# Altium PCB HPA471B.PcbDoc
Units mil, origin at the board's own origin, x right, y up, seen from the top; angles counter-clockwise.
Board outline 1305 x 1105 mil, 2 copper layers (Top Layer, Bottom Layer); 47 components, 32 nets, 115 pads, 21 vias.
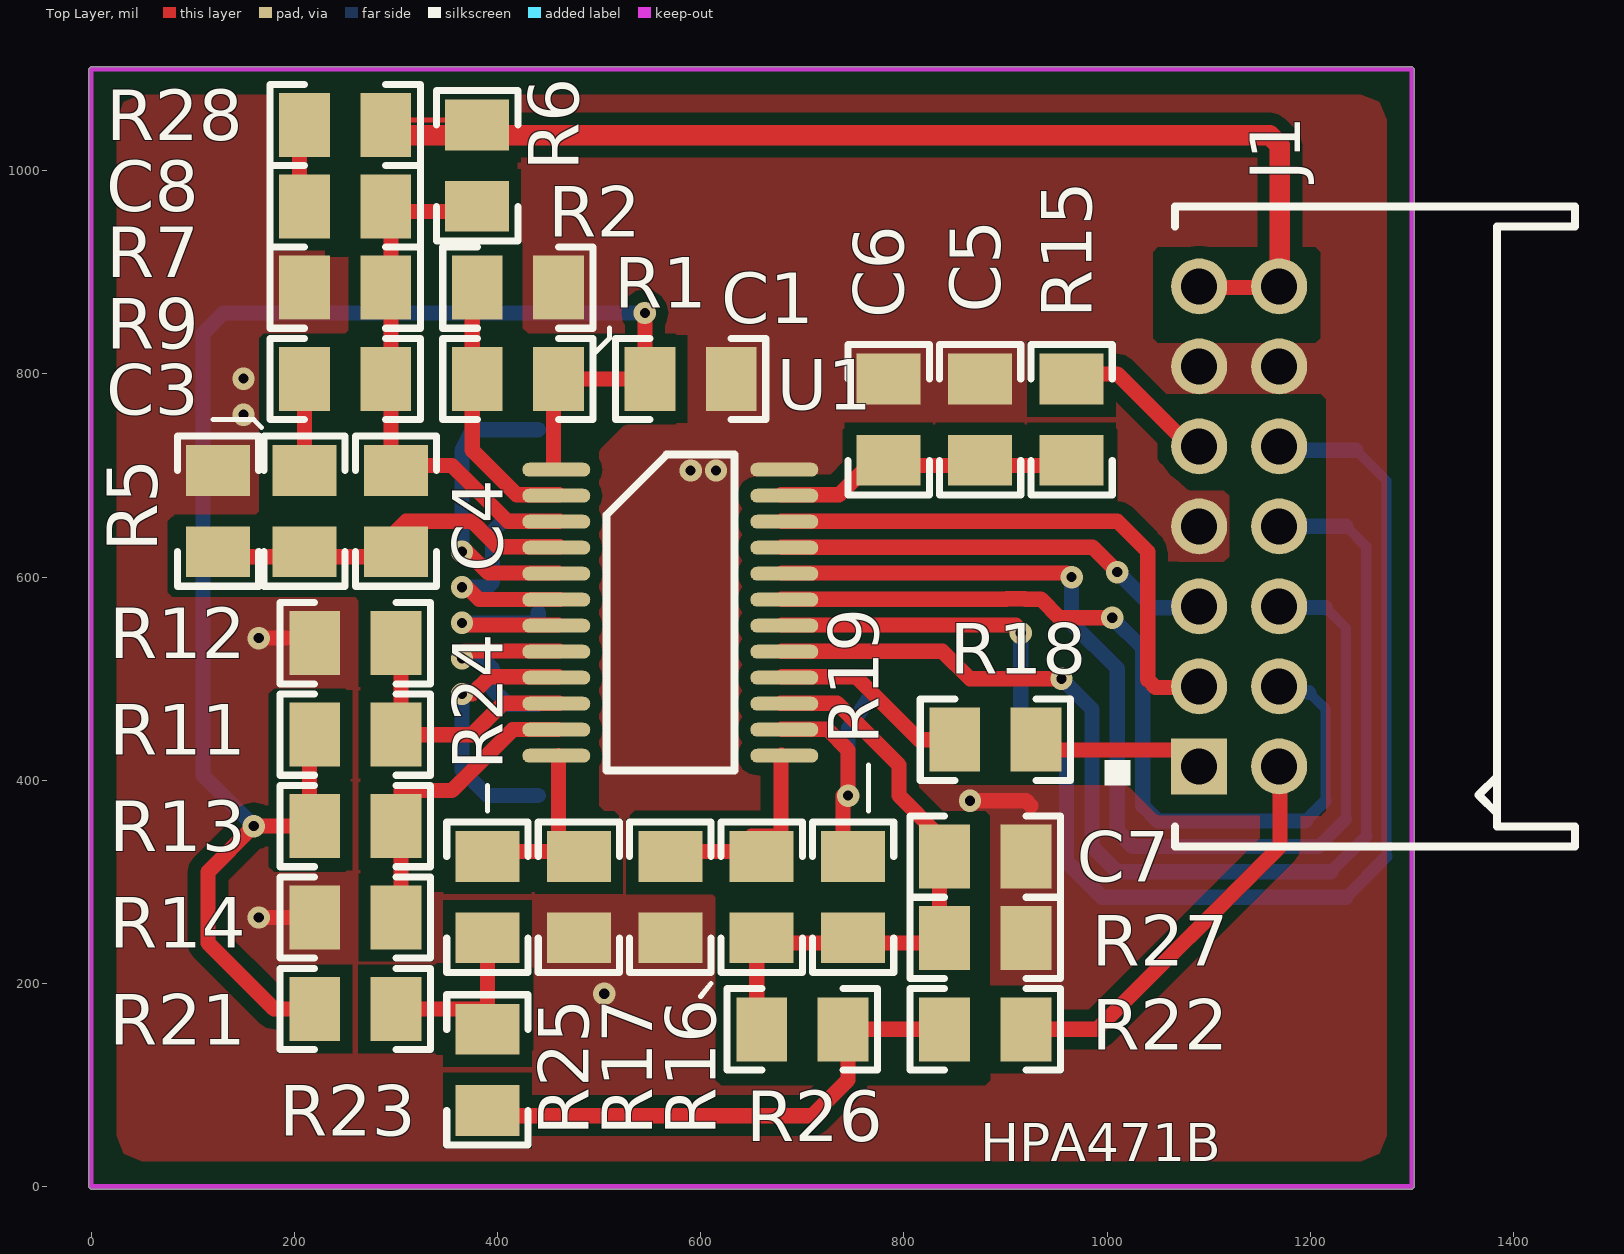
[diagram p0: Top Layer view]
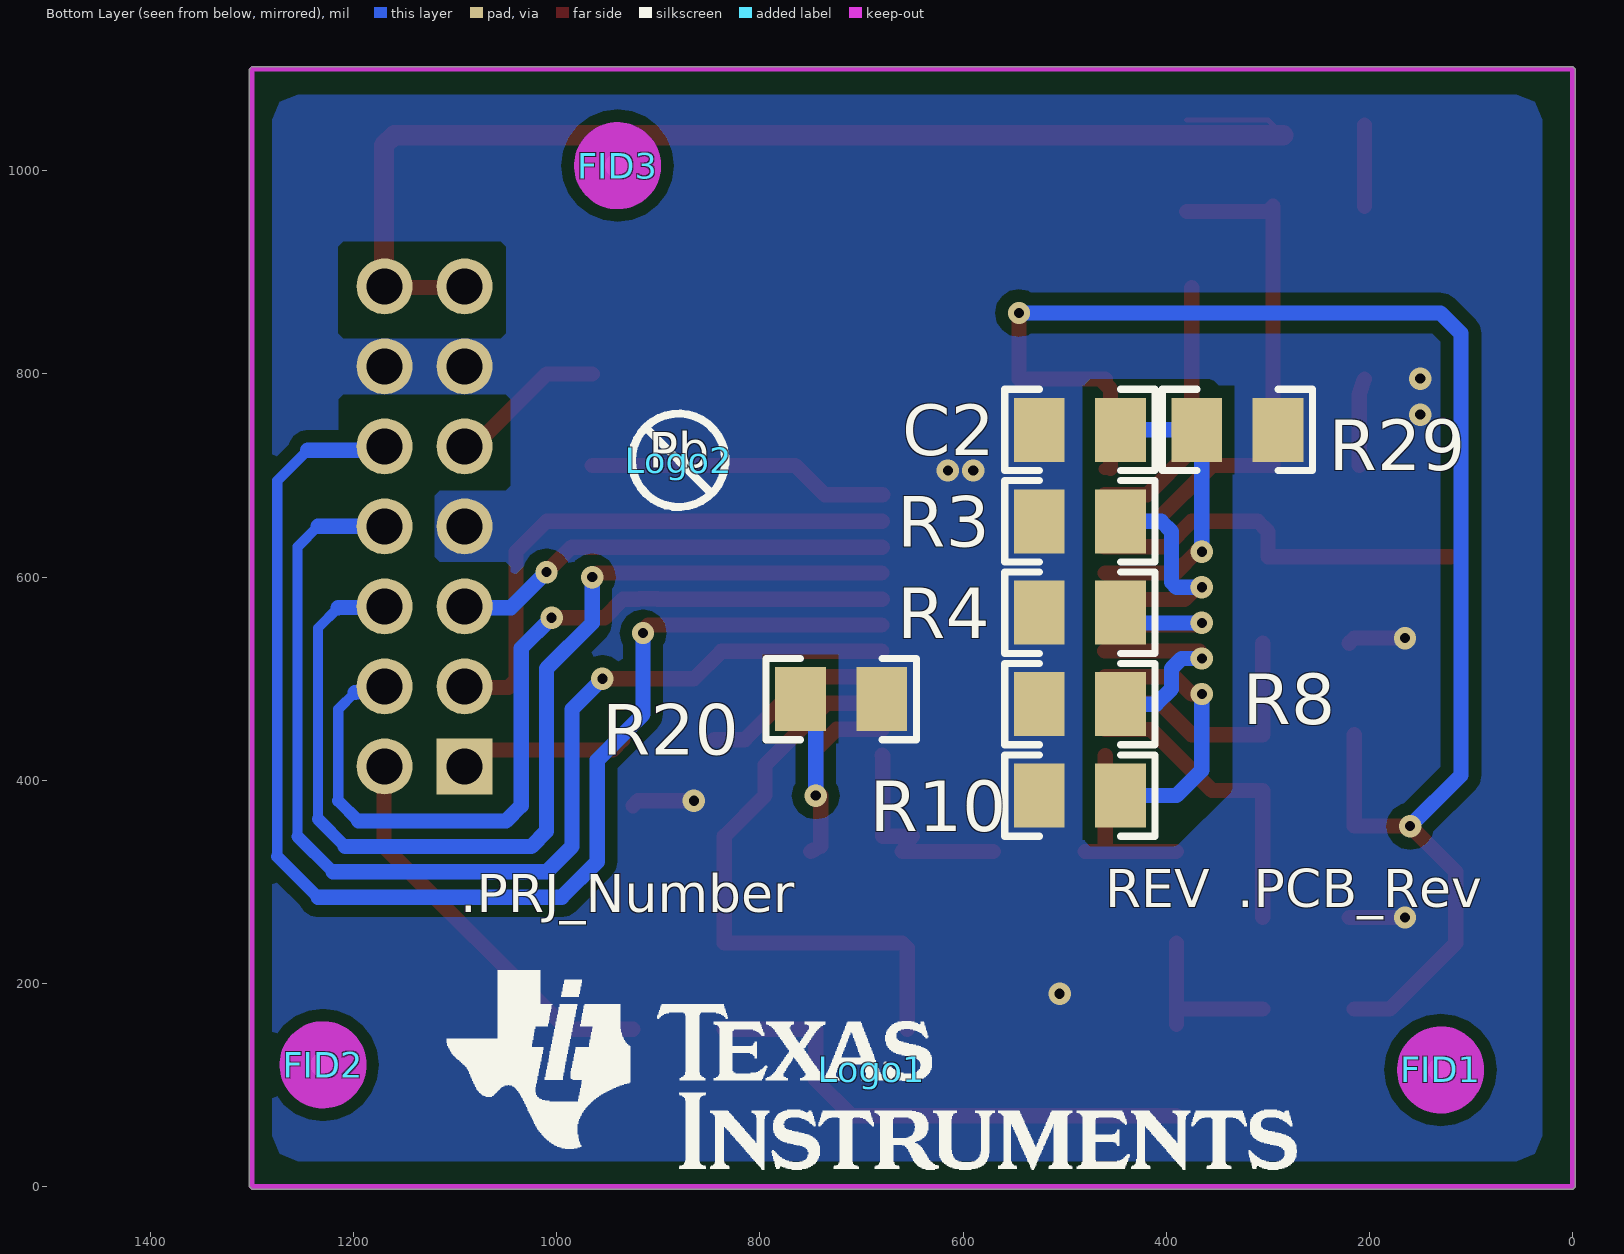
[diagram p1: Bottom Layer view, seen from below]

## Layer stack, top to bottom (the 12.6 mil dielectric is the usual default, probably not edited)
Top Layer: signal copper 2.8
Dielectric: core 12.6, FR-4, Dk 4.8
Bottom Layer: signal copper 2.8

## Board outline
-2.5,0 0,-2.5 1300,-2.5 1302.5,0 1302.5,1100 1300,1102.5 0,1102.5 -2.5,1100

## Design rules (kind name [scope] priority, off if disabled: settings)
AcuteAngle [All] p1: minimum=4.50000000000000E+0001 checktracksonly=TRUE
AssemblyTestPointUsage [All] p1: valid=2
Clearance Clearance_Poly [InPolygon] p1: gap=12
Clearance Clearance_BoardEdge_Poly [OnCopper and InPoly vs IsKeepOut] p2: gap=19.68
Clearance Clearance_BoardEdge [OnCopper and Not InComponentClass('Logo') and not InComponentClass('FiducialMark') and not InRegion(1000,500,4000,800) and Not IsKeepout vs IsKeepout] p3 off: gap=19.68
Clearance Clearance_ALL [All] p4: gap=8
ComponentClearance ComponentClearance_Logo [InComponentClass(Logo)] p1: gap=3.94 collisioncheckmode=3 verticalgap=27.56 showdistances=FALSE
ComponentClearance ComponentClearance_ScrewToNut [(HasFootprint('NY PMS 440 0025 PH')) vs (HasFootprint('Keystone_1902C'))] p2: gap=0 collisioncheckmode=3 verticalgap=0 showdistances=FALSE
ComponentClearance ComponentClearance_MountingHoles [InComponentClass('Mounting Holes')] p3: gap=19.68 collisioncheckmode=3 verticalgap=27.56 showdistances=FALSE
ComponentClearance ComponentClearance_SmallPassives [HasFootprint('0201*') or HasFootprint('0402*') or HasFootprint('0508') or HasFootprint('0603*') or HasFootprint('0612') or HasFootprint('0805*') or HasFootprint('0815*') or HasFootprint('0830*') or HasFootprint('1206*') or HasFootprint('1210*') or HasFootprint('1808*') or HasFootprint('1812*') or HasFootprint('1825*') or HasFootprint('2010*') or HasFootprint('2220*') or HasFootprint('2225*') or HasFootprint('2512*') or HasFootprint('2728*') or HasFootprint('3518*') vs HasFootprint('0201*') or HasFootprint('0402*') or HasFootprint('0508') or HasFootprint('0603*') or HasFootprint('0612') or HasFootprint('0805*') or HasFootprint('0815*') or HasFootprint('0830*') or HasFootprint('1206*') or HasFootprint('1210*') or HasFootprint('1808*') or HasFootprint('1812*') or HasFootprint('1825*') or HasFootprint('2010*') or HasFootprint('2220*') or HasFootprint('2225*') or HasFootprint('2512*') or HasFootprint('2728*') or HasFootprint('3518*')] p4: gap=7.87 collisioncheckmode=3 verticalgap=10 showdistances=FALSE
ComponentClearance ComponentClearance_THtoSMT [IsThruComponent vs IsSMTComponent] p5 off: gap=7.87 collisioncheckmode=3 verticalgap=27.56 showdistances=FALSE
ComponentClearance ComponentClearance_THtoTH [IsThruComponent vs IsThruComponent] p6 off: gap=7.87 collisioncheckmode=3 verticalgap=27.56 showdistances=FALSE
ComponentClearance [All] p7: gap=0 collisioncheckmode=3 verticalgap=0 showdistances=FALSE
DiffPairsRouting [All] p1: maxlimit=100 minlimit=10 mostfreqgap=10 maxuncoupledlength=1000
FabricationTestPointUsage TestPointUsage [All] p1: valid=2 allowmultiple=FALSE
FabricationTestpoint Testpoint [All] p1: side=3 testpointundercomponent=TRUE minsize=40 maxsize=100 preferedsize=60 minholesize=0 maxholesize=40 preferedholesize=32 testpointgrid=1 allowsidetop=TRUE allowsidebottom=TRUE usegrid=TRUE gridtolerance=0.01
FanoutControl Fanout_LCC [IsLCC] p1: bgadir=Out bgaviamode=Centered fanoutstyle=Auto fanoutdirection=Alternating viagrid=1 // Fanout_LCC (Default Rule)
FanoutControl Fanout_BGA [IsBGA] p2: bgadir=Out bgaviamode=Centered fanoutstyle=Auto fanoutdirection=Alternating viagrid=1 // Fanout_BGA (Default Rule)
FanoutControl Fanout_Default [All] p4: bgadir=Out bgaviamode=Centered fanoutstyle=Auto fanoutdirection=Alternating viagrid=1 // Fanout_Default (Default Rule)
FanoutControl Fanout_Small [(CompPinCount < 5)] p5: bgadir=Out bgaviamode=Centered fanoutstyle=Auto fanoutdirection=OutThenIn viagrid=1 // Fanout_Small (Default Rule)
Height "Height Bottom" [(OnLayer('Bottom Layer'))] p1: minheight=0 maxheight=1000 prefheight=500
Height Height_top [(OnLayer('Top Layer'))] p2: minheight=0 maxheight=1750 prefheight=1750
HoleSize [All] p1: absolutevalues=TRUE maxlimit=275.59 minlimit=8 maxpercent=80.000 minpercent=20.000
MinimumAnnularRing [All] p1: minimumring=6
MinimumSolderMaskSliver MinimumSolderMaskSliver_Logo [InComponentClass('Logo') vs InComponentClass('Logo')] p1: minsoldermaskwidth=0.7
MinimumSolderMaskSliver [All] p2: minsoldermaskwidth=4
PlaneConnect [All] p1: planeconnectstyle=Relief reliefexpansion=10 reliefentries=4 reliefconductorwidth=10 reliefairgap=10
PolygonConnect PolygonConnect_23 [All vs IsNamedPolygon('Top Layer, Top-PWRGND 4')] p1: connectstyle=Direct reliefconductorwidth=10 reliefentries=4 polygonreliefangle="90 Angle" airgapwidth=10
PolygonConnect PolygonConnect_22 [All vs IsNamedPolygon('Top Layer, Top-PWRGND 4')] p2: connectstyle=Direct reliefconductorwidth=10 reliefentries=4 polygonreliefangle="90 Angle" airgapwidth=10
PolygonConnect PolygonConnect_21 [All vs IsNamedPolygon('Top Layer, Top-PWRGND 2')] p3: connectstyle=Direct reliefconductorwidth=10 reliefentries=4 polygonreliefangle="90 Angle" airgapwidth=10
PolygonConnect PolygonConnect_20 [All vs IsNamedPolygon('Top Layer, Top-PWRGND 3')] p4: connectstyle=Direct reliefconductorwidth=10 reliefentries=4 polygonreliefangle="90 Angle" airgapwidth=10
PolygonConnect PolygonConnect_19 [All vs IsNamedPolygon('Top Layer, Top-PWRGND 4')] p5: connectstyle=Direct reliefconductorwidth=10 reliefentries=4 polygonreliefangle="90 Angle" airgapwidth=10
PolygonConnect PolygonConnect_18 [All vs IsNamedPolygon('Top Layer, Top-GND')] p6: connectstyle=Direct reliefconductorwidth=10 reliefentries=4 polygonreliefangle="90 Angle" airgapwidth=10
PolygonConnect PolygonConnect_17 [All vs IsNamedPolygon('Top Layer, Top-GND 1')] p7: connectstyle=Direct reliefconductorwidth=10 reliefentries=4 polygonreliefangle="90 Angle" airgapwidth=10
PolygonConnect PolygonConnect_16 [All vs IsNamedPolygon('Top Layer, Top-GND 2')] p8: connectstyle=Direct reliefconductorwidth=10 reliefentries=4 polygonreliefangle="90 Angle" airgapwidth=10
PolygonConnect PolygonConnect_15 [All vs IsNamedPolygon('Top Layer, Top-NET00002')] p9: connectstyle=Direct reliefconductorwidth=10 reliefentries=4 polygonreliefangle="90 Angle" airgapwidth=10
PolygonConnect PolygonConnect_14 [All vs IsNamedPolygon('Top Layer, Top-NET00003')] p10: connectstyle=Direct reliefconductorwidth=10 reliefentries=4 polygonreliefangle="90 Angle" airgapwidth=10
PolygonConnect PolygonConnect_13 [All vs IsNamedPolygon('Top Layer, Top-NET00003')] p11: connectstyle=Direct reliefconductorwidth=10 reliefentries=4 polygonreliefangle="90 Angle" airgapwidth=10
PolygonConnect PolygonConnect_12 [All vs IsNamedPolygon('Top Layer, Top-NET00007')] p12: connectstyle=Direct reliefconductorwidth=10 reliefentries=4 polygonreliefangle="90 Angle" airgapwidth=10
PolygonConnect PolygonConnect_11 [All vs IsNamedPolygon('Top Layer, Top-NET00016')] p13: connectstyle=Direct reliefconductorwidth=10 reliefentries=4 polygonreliefangle="90 Angle" airgapwidth=10
PolygonConnect PolygonConnect_10 [All vs IsNamedPolygon('Top Layer, Top-NET00025')] p14: connectstyle=Direct reliefconductorwidth=10 reliefentries=4 polygonreliefangle="90 Angle" airgapwidth=10
PolygonConnect PolygonConnect_9 [All vs IsNamedPolygon('Top Layer, Top-NET00025 1')] p15: connectstyle=Direct reliefconductorwidth=10 reliefentries=4 polygonreliefangle="90 Angle" airgapwidth=10
PolygonConnect PolygonConnect_8 [All vs IsNamedPolygon('Top Layer, Top-No Net')] p16: connectstyle=Direct reliefconductorwidth=10 reliefentries=4 polygonreliefangle="90 Angle" airgapwidth=10
PolygonConnect PolygonConnect_7 [All vs IsNamedPolygon('Top Layer, Top-PWRGND')] p17: connectstyle=Direct reliefconductorwidth=10 reliefentries=4 polygonreliefangle="90 Angle" airgapwidth=10
PolygonConnect PolygonConnect_6 [All vs IsNamedPolygon('Top Layer, Top-PWRGND 1')] p18: connectstyle=Direct reliefconductorwidth=10 reliefentries=4 polygonreliefangle="90 Angle" airgapwidth=10
PolygonConnect PolygonConnect_5 [All vs IsNamedPolygon('Top Layer, Top-PWRGND 2')] p19: connectstyle=Direct reliefconductorwidth=10 reliefentries=4 polygonreliefangle="90 Angle" airgapwidth=10
PolygonConnect PolygonConnect_4 [All vs IsNamedPolygon('Top Layer, Top-PWRGND 3')] p20: connectstyle=Direct reliefconductorwidth=10 reliefentries=4 polygonreliefangle="90 Angle" airgapwidth=10
PolygonConnect PolygonConnect_3 [All vs IsNamedPolygon('Top Layer, Top-PWRGND 4')] p21: connectstyle=Direct reliefconductorwidth=10 reliefentries=4 polygonreliefangle="90 Angle" airgapwidth=10
PolygonConnect PolygonConnect_2 [All vs IsNamedPolygon('Top Layer, Top-PWRGND 3') Or  IsNamedPolygon('Top Layer, Top-PWRGND 4')] p22: connectstyle=Direct reliefconductorwidth=10 reliefentries=4 polygonreliefangle="90 Angle" airgapwidth=10
PolygonConnect PolygonConnect_1 [All vs IsNamedPolygon('Top Layer, Top-PWRGND 2') Or  IsNamedPolygon('Bottom Layer, Bottom-GND') Or  IsNamedPolygon('Bottom Layer, Bottom-NET00038') Or  IsNamedPolygon('Bottom Layer, Bottom-NET00006') Or  IsNamedPolygon('Bottom Layer, Bottom-NET00003') Or  IsNamedPolygon('Bottom Layer, Bottom-NET00004 2') Or  IsNamedPolygon('Bottom Layer, Bottom-NET00020') Or  IsNamedPolygon('Bottom Layer, Bottom-GND 2') Or  IsNamedPolygon('Bottom Layer, Bottom-NET00004') Or  IsNamedPolygon('Bottom Layer, Bottom-PWRGND') Or  IsNamedPolygon('Bottom Layer, Bottom-NET00002 1') Or  IsNamedPolygon('Bottom Layer, Bottom-NET00013') Or  IsNamedPolygon('Bottom Layer, Bottom-NET00012') Or  IsNamedPolygon('Bottom Layer, Bottom-NET00004 3') Or  IsNamedPolygon('Bottom Layer, Bottom-NET00004 1') Or  IsNamedPolygon('Bottom Layer, Bottom-NET00016') Or  IsNamedPolygon('Bottom Layer, Bottom-GND 1') Or  IsNamedPolygon('Bottom Layer, Bottom-NET00025') Or  IsNamedPolygon('Bottom Layer, Bottom-NET00002') Or  IsNamedPolygon('Top Layer, Top-No Net') Or  IsNamedPolygon('Top Layer, Top-NET00016') Or  IsNamedPolygon('Top Layer, Top-NET00025 1') Or  IsNamedPolygon('Top Layer, Top-GND 2') Or  IsNamedPolygon('Top Layer, Top-PWRGND 3') Or  IsNamedPolygon('Top Layer, Top-PWRGND 4') Or  IsNamedPolygon('Top Layer, Top-NET00002') Or  IsNamedPolygon('Top Layer, Top-NET00007') Or  IsNamedPolygon('Top Layer, Top-GND 1') Or  IsNamedPolygon('Top Layer, Top-PWRGND 1') Or  IsNamedPolygon('Top Layer, Top-GND') Or  IsNamedPolygon('Top Layer, Top-NET00025') Or  IsNamedPolygon('Top Layer, Top-NET00003') Or  IsNamedPolygon('Top Layer, Top-PWRGND')] p23: connectstyle=Direct reliefconductorwidth=10 reliefentries=4 polygonreliefangle="90 Angle" airgapwidth=10
PolygonConnect [All] p24: connectstyle=Relief reliefconductorwidth=10 reliefentries=4 polygonreliefangle="90 Angle" airgapwidth=10
RoutingVias [All] p1: holewidth=16 width=34 viastyle="Through Hole" minholewidth=6 minwidth=10 maxholewidth=40 maxwidth=65
SMDToCorner [All] p1 off: distance=30000
SilkToSilkClearance [All] p1 off: silktosilkclearance=4.5
SilkscreenOverComponentPads [All] p1 off: minsilkscreentomaskgap=5
SolderMaskExpansion [All] p1: expansion=3
Width [All] p1: maxlimit=100 minlimit=10 preferedwidth=31.5 checkconnectedcopper=TRUE
13 further rules are at their usual default settings.

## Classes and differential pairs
component class HPA471B_Hardware: !PCB FID1 FID2 FID3 Logo1 Logo2 ZZ1 ZZ2 ZZ3
component class HPA471B_Sht01: C1 C2 C3 C4 C5 C6 C7 C8 J1 R1 R2 R3 R4 R5 R6 R7 R8 R9 R10 R11 R12 R13 R14 R15 R16 R17 R18 R19 R20 R21 R22 R23 R24 R25 R26 R27 R28 R29 U1

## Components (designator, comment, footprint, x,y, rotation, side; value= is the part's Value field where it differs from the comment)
C1 "08055C105KAT2A" 0805_HV 590,795 r180 top
C2 "C0805C154K5RACTU" 0805_HV 485,745 r180 bottom
C3 "08055C562KAT2A" 0805_HV 210,665 r90 top
C4 "08055C561KAT2A" 0805_HV 300,665 r90 top
C5 "08055C105KAT2A" 0805_HV 875,755 r270 top
C6 "08053C104KAT2A" 0805_HV 785,755 r270 top
C7 "08055C331KAT2A" 0805_HV 880,325 r180 top
C8 "08055C331KAT2A" 0805_HV 250,965 r180 top
FID1 "Fiducial" Fiducial6.4-20 130,115 r180 bottom
FID2 "Fiducial" Fiducial6.4-20 1230,120 r180 bottom
FID3 "Fiducial" Fiducial6.4-20 940,1005 r180 bottom
J1 "DF11-14DP-2DS(52)" Hirose_DF11-14DP-2DS_52 1130,650 r90 top
Logo1 "Texas Instruments" TI_Stacked_Overlay_Small 690,115 r180 bottom
Logo2 "Pb-Free Symbol" Pb-Free_Overlay_Small 880,715 r180 bottom
R1 "CRCW08052K37FKEA" 0805_HV 420,795 r0 top
R2 "CRCW08052K37FKEA" 0805_HV 420,885 r180 top
R3 "CRCW080512K1FKEA" 0805_HV 485,655 r180 bottom
R4 "CRCW080512K1FKEA" 0805_HV 485,565 r180 bottom
R5 "CRCW08051K00FKEA" 0805_HV 125,665 r90 top
R6 "CRCW08059K09FKEA" 0805_HV 380,1005 r90 top
R7 "CRCW08052K37FKEA" 0805_HV 250,885 r0 top
R8 "CRCW080556K2FKEA" 0805_HV 485,475 r180 bottom
R9 "CRCW080527K4FKEA" 0805_HV 250,795 r0 top
R10 "CRCW080513K3FKEA" 0805_HV 485,385 r180 bottom
R11 "CRCW080561K9FKEA" 0805_HV 260,445 r0 top
R12 "CRCW08051K00FKEA" 0805_HV 260,535 r0 top
R13 "CRCW08051K00FKEA" 0805_HV 260,355 r180 top
R14 "CRCW0805127KFKEA" 0805_HV 260,265 r0 top
R15 "CRCW080522R6FKEA" 0805_HV 965,755 r90 top
R16 "CRCW08051K00FKEA" 0805_HV 660,285 r270 top
R17 "CRCW08050000Z0EA" 0805_HV 570,285 r90 top
R18 "CRCW08051K00FKEA" 0805_HV 890,440 r0 top
R19 "CRCW08051K00FKEA" 0805_HV 750,285 r270 top
R20 "CRCW08050000Z0EA" 0805_HV 720,480 r0 bottom
R21 "CRCW08050000Z0EA" 0805_HV 260,175 r180 top
R22 "CRCW08051K00FKEA" 0805_HV 880,155 r0 top
R23 "CRCW08051K00FKEA" 0805_HV 390,115 r270 top
R24 "CRCW080516K9FKEA" 0805_HV 390,285 r270 top
R25 "CRCW08051K00FKEA" 0805_HV 480,285 r90 top
R26 "CRCW08050000Z0EA" 0805_HV 700,155 r0 top
R27 "CRCW08051K00FKEA" 0805_HV 880,245 r180 top
R28 "CRCW08051K00FKEA" 0805_HV 250,1045 r0 top
R29 "CRCW0805825KFKEA" 0805_HV 330,745 r0 bottom
U1 "UCC28950PW" PW0024A_N 570,565 r0 top
ZZ1 "These assemblies are ESD sensitive, ESD precautions shall be observed." AssemblyNote -120,6695 r0 top
ZZ2 "These assemblies must be clean and free from flux and all contaminants. Use of no clean flux is not acceptable." AssemblyNote -120,6590 r0 top
ZZ3 "These assemblies must comply with workmanship standards IPC-A-610 Class 2, unless otherwise specified." AssemblyNote -120,6470 r0 top

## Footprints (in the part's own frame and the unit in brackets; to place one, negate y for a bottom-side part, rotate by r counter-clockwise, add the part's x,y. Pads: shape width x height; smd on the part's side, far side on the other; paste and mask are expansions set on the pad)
0805_HV [mil] "0805 with 30mil clearance between pads"
  rect 50x63 smd: 1(-40,0) 2(40,0)
  silkscreen extent -74,-40 74,40, body extent -43,-29 43,29, height 43
AssemblyNote [mil] "Assembly Note"
Fiducial6.4-20 [mil]
  round 25 smd mask+26.87: 1(0,0)
  Top Layer keep-out circle w46.37: c0,0 r19.68
Hirose_DF11-14DP-2DS_52 [mm] "TH, 14-Leads, Body 16x10mm, Pitch 2mm"
  rect 1.4x1.4 hole 0.9: 1(-6,1)
  round 1.4 hole 0.9: 2(-6,-1) 3(-4,1) 4(-4,-1) 5(-2,1) 6(-2,-1) 7(0,1) 8(0,-1) 9(2,1) 10(2,-1) 11(4,1) 12(4,-1) 13(6,1) 14(6,-1)
  silkscreen extent -8,-8.4 8,1.6, body extent -8,-8.4 8,1.6, height 5
Pb-Free_Overlay_Small [mil]
  silkscreen extent -46,-46 46,46
PW0024A_N [mm] "TSOP, 24-Leads, Body 7.8x4.4mm, Pitch 0.65mm, IPC Medium Density"
  oval 1.7x0.35 smd: 1(-2.85,3.575) 2(-2.85,2.925) 3(-2.85,2.275) 4(-2.85,1.625) 5(-2.85,0.975) 6(-2.85,0.325) 7(-2.85,-0.325) 8(-2.85,-0.975) 9(-2.85,-1.625) 10(-2.85,-2.275) 11(-2.85,-2.925) 12(-2.85,-3.575) 13(2.85,-3.575) 14(2.85,-2.925) 15(2.85,-2.275) 16(2.85,-1.625) 17(2.85,-0.975) 18(2.85,-0.325) 19(2.85,0.325) 20(2.85,0.975) 21(2.85,1.625) 22(2.85,2.275) 23(2.85,2.925) 24(2.85,3.575)
  silkscreen extent -1.6,-3.95 1.6,3.95, body extent -3.21,-3.9 3.21,3.9, height 0.98
TI_Stacked_Overlay_Small [mil]
  silkscreen extent -418,-98 418,98

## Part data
C1 C5: "CAP, CERM, 1 µF, 50 V, +/- 10%, X7R, 0805"
C2: "CAP, CERM, 0.15 µF, 50 V, +/- 10%, X7R, 0805"
C3: "CAP, CERM, 5600 pF, 50 V, +/- 10%, X7R, 0805"
C4: "CAP, CERM, 560 pF, 50 V, +/- 10%, X7R, 0805"
C6: "CAP, CERM, 0.1 µF, 25 V, +/- 10%, X7R, 0805"
C7 C8: "CAP, CERM, 330 pF, 50 V, +/- 10%, X7R, 0805"
FID1 FID2 FID3: "Fiducial mark.  There is nothing to buy or mount."
J1: "Header (shrouded), 2 mm, 7x2, R/A, TH"
Logo1: library part TI_Logo, "Texas Instrument Corporate Signature"
Logo2: library part Pb-Free
R1 R2 R7: "RES, 2.37k ohm, 1%, 0.125W, 0805"
R3 R4: "RES, 12.1k ohm, 1%, 0.125W, 0805"
R5 R12 R13 R16 R18 R19 R22 R23 R25 R27 R28: "RES, 1.00k ohm, 1%, 0.125W, 0805"
R6: "RES, 9.09k ohm, 1%, 0.125W, 0805"
R8: "RES, 56.2k ohm, 1%, 0.125W, 0805"
R9: "RES, 27.4k ohm, 1%, 0.125W, 0805"
R10: "RES, 13.3 k, 1%, 0.125 W, 0805"
R11: "RES, 61.9k ohm, 1%, 0.125W, 0805"
R14: "RES, 127k ohm, 1%, 0.125W, 0805"
R15: "RES, 22.6 ohm, 1%, 0.125W, 0805"
R17 R20 R21 R26: "RES, 0 ohm, 5%, 0.125W, 0805"
R24: "RES, 16.9k ohm, 1%, 0.125W, 0805"
R29: "RES, 825k ohm, 1%, 0.125W, 0805"
U1: "Green Phase-Shifted Full-Bridge Controller with Synchronous Rectification with Current Control, 97 % Duty Cycle, -40 to +125 degC, 24-pin TSSOP (PW), Green (RoHS & no Sb/Br)"
ZZ1 ZZ2 ZZ3: library part AssemblyNote

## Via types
v1: diameter 22, hole 10, Top Layer to Bottom Layer, 21 vias

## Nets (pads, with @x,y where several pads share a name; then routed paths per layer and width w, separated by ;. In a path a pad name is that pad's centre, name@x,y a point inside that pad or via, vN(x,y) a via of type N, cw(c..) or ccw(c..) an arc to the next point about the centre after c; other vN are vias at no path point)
ADEL: R19.1 R20.2 U1.14 | length 286.1
  Top Layer w15: U1.14@679.5,450.3 724.7,450.3 745,430 v1(745,385) 740,385 740,335 R19.1@750,330
  Bottom Layer w15: v1(745,385) 745,450 R20.2@765,480
ADELEF: R16.1 R17.2 U1.13 | length 216.9
  Top Layer w15: R17.2@570,330 660,330 650,345 679,345 679,424.2 U1.13@679.5,424.7
COMP: C3.1 C4.1 R5.1 U1.4 | length 381.1
  Top Layer w12: U1.4@460.5,629.6 U1.4@461,630
  Top Layer w15: R5.1@120,620 300,620 300,645 310,655 375,655 400,630 U1.4@461,630
CS: J1.2 R22.2 | length 402.1
  Top Layer w15: R22.2@925,155 990,155 1170,335 1170,415 J1.2@1168.7,412.8
CS0: C7.2 R16.2 R19.2 R26.1 R27.2 U1.15 | length 595.4
  Top Layer w12: U1.15@679,476 U1.15@679.5,475.9
  Top Layer w15: R26.1@655,155 655,235 660,240 665,240 750,240 795,240 835,240 835,245 835,325 835,345 795,385 795,415 734,476 U1.15@679,476
DCM: R24.1 R25.2 U1.12 | length 184.3
  Top Layer w15: R24.1@390,330 R25.2@460,330 ; U1.12@460,424.25 R25.2@460,330 ; R25.2@480,330 R25.2@460,330
DELAB: R3.2 U1.6 | length 234.7
  Top Layer w12: U1.6@460.5,578.4 U1.6@462,578
  Top Layer w15: v1(365,590) 370,590 382,578 U1.6@462,578
  Bottom Layer w15: v1(365,590) 390,590 395,595 395,645 405,655 R3.2@440,655
DELCD: R4.2 U1.7 | length 182.5
  Top Layer w12: U1.7@460,553 U1.7@460.5,552.8
  Top Layer w15: v1(365,555) 365,553 U1.7@460,553
  Bottom Layer w15: v1(365,555) 440,555 R4.2@440,565
DELEF: R8.2 U1.8 | length 206.2
  Top Layer w15: v1(365,520) 367.2,527.2 U1.8@460.5,527.2
  Bottom Layer w15: v1(365,520) 385,520 395,510 395,490 410,475 R8.2@440,475
EA+: R1.1 R2.2 U1.2 | length 263.9
  Top Layer w15: R2.2@375,885 375,725 419,681 460.5,681 U1.2@460.5,680.8
EA-: C4.2 C8.1 R6.1 R7.2 R9.2 U1.3 | length 531.4
  Top Layer w12: U1.3@460.5,655.2 U1.3@461,655
  Top Layer w15: R6.1@380,960 300,960 295,965 295,885 295,795 295,710 300,710 355,710 410,655 U1.3@461,655
GND: C1.1 C2.1 C5.1 C6.1 C7.1 J1.7 J1.11 J1.12 R2.1 R3.1 R4.1 R5.2 R7.1 R8.1 R10.1 R12.1 R14.1 R17.1 R20.1 R25.1 R27.1 R29.1 U1.24 | length 174.1
  Top Layer w15: v1(165,265) R14.1 ; v1(165,540) 215,540 R12.1 ; v1(865,380) 920,380 925,375
  other v1: 505,190 590,705 615,705 150,760 150,795.42
NetC3_2: C3.2 R9.1 | length 85.8
  Top Layer w15: R9.1@205,795 210,780 C3.2@210,710
NetC8_2: C8.2 R28.1 | length 80
  Top Layer w15: C8.2@205,965 R28.1@205,1045
NetR21_1: R21.1 R23.1 R24.2 | length 165
  Top Layer w15: R21.1@305,175 R23.1@390,175 ; R23.1@390,160 R23.1@390,175 ; R24.2@390,240 R23.1@390,175
NetR22_1: R22.1 R23.2 R26.2 | length 509.5
  Top Layer w15: R23.2@390,70 710,70 745,105 745,155 R22.1@835,155
OUTA: J1.3 U1.22 | length 552
  Top Layer w15: U1.22@679.5,655.1 1010,655 1040,625 1040,499 1047.5,491.5 J1.3@1090,491.5
OUTB: J1.5 U1.21 | length 436.1
  Top Layer w12: U1.21@679.5,629.5 U1.21@680,630
  Top Layer w15: U1.21@679.5,629.5 985.5,629.5 v1(1010,605)
  Bottom Layer w15: v1(1010,605) 1045,570 1090,570 J1.5@1090,570.2
OUTC: J1.6 U1.20 | length 1060.5
  Top Layer w12: U1.20@679.5,603.9 U1.20@680,604
  Top Layer w15: U1.20@680,604 960,604 v1(965,600)
  Bottom Layer w10: 1215,570 1235,550 1235,361.98
  Bottom Layer w12: 1208.02,335 1235,361.98
  Bottom Layer w15: v1(965,600) 965,555 1010,510 1010,350 1025,335 1208.02,335 ; J1.6@1168.7,570.2 1215,570
OUTD: J1.4 U1.19 | length 869
  Top Layer w15: U1.19@679.5,578.3 900.66,578.3 901.19,578.84 918.81,578.84 919.34,578.3 934.7,578.3 953,560 v1(1005,560)
  Bottom Layer w10: 1198.5,486.5 1215,470 1215,380
  Bottom Layer w12: 1195,360 1215,380
  Bottom Layer w15: v1(1005,560) 1035,530 1035,375 1050,360 1195,360 ; J1.4@1168.7,491.5 1198.5,486.5
OUTE: J1.10 U1.18 | length 1321.9
  Top Layer w12: U1.18@679.5,552.7 U1.18@680,553
  Top Layer w15: U1.18@680,553 910,553 v1(915,545)
  Bottom Layer w10: 1245,725 1275,695 1275,325
  Bottom Layer w12: 1235,285 1275,325
  Bottom Layer w15: v1(915,545) 915,465 960,420 960,320 995,285 1235,285 ; J1.10@1168.7,727.6 1170,730 1175,725 1245,725
OUTF: J1.8 U1.17 | length 1139.1
  Top Layer w12: U1.17@679.5,527.1 U1.17@680,527
  Top Layer w15: U1.17@680,527 838,527 865,500 v1(955,500)
  Bottom Layer w10: 1235,650 1255,630 1255,344.83
  Bottom Layer w12: 1220.17,310 1255,344.83
  Bottom Layer w15: v1(955,500) 985,470 985,335 1010,310 1220.17,310 ; J1.8@1168.7,648.9 1170,650 1235,650
RSUM: R13.1 R14.2 U1.11 | length 305.5
  Top Layer w12: U1.11@460,450 U1.11@460.5,450.4
  Top Layer w15: R14.2@305,265 305,355 305,390 355,390 415,450 U1.11@460,450
RT: R11.2 R12.2 U1.10 | length 258.8
  Top Layer w12: U1.10@460.5,476 U1.10@461,476
  Top Layer w15: R12.2@305,535 305,445 375,445 406,476 U1.10@460.5,476
SS/EN: C2.2 R29.2 U1.5 | length 291.6
  Top Layer w12: U1.5@460,604 U1.5@460.5,604
  Top Layer w15: v1(365,625) 370,625 391,604 U1.5@460,604
  Bottom Layer w15: v1(365,625) 365,725 375,745 C2.2@440,745
SYNC: J1.1 R18.2 | length 173.4
  Top Layer w15: R18.2@935,440 945,430 1085,430 1090,425 J1.1@1090,412.8
SYNC0: R18.1 U1.16 | length 191.4
  Top Layer w12: U1.16@679.5,501.5 U1.16@680,502
  Top Layer w15: U1.16@680,502 753,502 815,440 R18.1@845,440
TMIN: R10.2 U1.9 | length 263
  Top Layer w12: U1.9@460,502 U1.9@460.5,501.6
  Top Layer w15: v1(365,485) 375,485 392,502 U1.9@460,502
  Bottom Layer w15: v1(365,485) 365,410 390,385 R10.2@440,385
VBIAS: J1.9 R15.2 | length 156.4
  Top Layer w15: R15.2@965,800 1010,800 1080,730 1090,730 J1.9@1090,727.6
VDD: C5.2 C6.2 R15.1 U1.23 | length 298.6
  Top Layer w12: U1.23@679,681 U1.23@679.5,680.7
  Top Layer w15: U1.23@679,681 736,681 765,710 785,710 875,710 R15.1@965,710
VOUT: J1.13 J1.14 R6.2 R28.2 | length 1227.4
  Top Layer w5: R28.2@285,1035 300,1050 R6.2@380,1050
  Top Layer w15: J1.13@1090,885 1168.7,885 J1.14@1170,885 ; J1.14@1175,890 J1.14@1180,895
  Top Layer w20: R28.2@285,1035 1160,1035 1170,1025 1170,885 1175,885 J1.14@1175,890
VREF: C1.2 R1.2 R11.1 R13.2 R21.2 U1.1 | length 1602.4
  Top Layer w12: U1.1@455,707 455.6,706.4 U1.1@460.5,706.4
  Top Layer w15: R21.2@215,175 180,175 115,240 115,310 v1(160,355) 215,355 R11.1@215,445 ; U1.1@455,707 455,785 R1.2@465,795 ; R1.2 R1.2@465,795 ; v1(545,860) 545,795 R1.2@465,795
  Bottom Layer w15: v1(160,355) 110,405 110,840 130,860 v1(545,860)
pads on no net: FID1.1 FID2.1 FID3.1

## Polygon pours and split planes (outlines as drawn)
GND on Top Layer "Top Layer, Top-GND 2" (solid, remove dead copper, pour order 6): 25,50 32.32,32.32 50,25 1250,25 1267.68,32.32 1275,50 1275,1050 1267.68,1067.68 1250,1075 50,1075 32.32,1067.68 25,1050
GND on Top Layer "Top Layer, Top-GND 1" (solid, pour order 4): 1060,830 1055,825 1055,790 1060,785 1200,785 1205,790 1205,825 1200,830
GND on Top Layer "Top Layer, Top-GND" (solid, pour order 2): 1055,690 1050,685 1050,637.07 1051.47,633.54 1073.54,611.46 1077.07,610 1115,610 1120,615 1120,685 1115,690
GND on Bottom Layer "Bottom Layer, Bottom-GND 2" (solid, remove dead copper, pour order 12): 30,50 37.32,32.32 55,25 1255,25 1272.68,32.32 1280,50 1280,1050 1272.68,1067.68 1255,1075 55,1075 37.32,1067.68 30,1050
GND on Bottom Layer "Bottom Layer, Bottom-GND 1" (solid, pour order 10): 1050,830 1045,825 1045,790 1050,785 1215,785 1220,790 1220,825 1215,830
GND on Bottom Layer "Bottom Layer, Bottom-GND" (solid, pour order 8): 1055,690 1050,685 1050,637.07 1051.47,633.54 1073.54,611.46 1077.07,610 1115,610 1120,615 1120,685 1115,690

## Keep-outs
Keep-Out Layer, Board:
  lines w5: 0,0 1300,0 1300,1100 0,1100 0,0

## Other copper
Top Layer:
  pour cut-out: 505,370 500,375 500,415 500,722.93 501.47,726.46 523.54,748.54 527.07,750 575,750 580,755 580,835 575,840 430,840 425,845 425,927.93 423.53,931.46 410.35,944.65 409.59,945.27 396.26,954.16 393.49,955 310,955 305,950 305,935 300,930 260,930 255,925 255,845 250,840 170,840 165,835 165,665 160,660 80,660 75,655 75,585 80,580 260,580 265,575 265,295 270,290 515,290 520,295 520,365 515,370
  pour cut-out: 225,1075 230,915 420,920 420,1075
  pour cut-out: 1048.54,366.46 1052.07,365 1210,365 1215,370 1215,775 1210,780 1055,780 1050,775 1050,717.07 1051.47,713.54 1078.54,686.46 1082.07,685 1115,685 1120,680 1120,620 1115,615 1055,615 1050,610 1050,485 1045,480 850,480 845,475 845,400 850,395 1017.93,395 1021.46,393.54
  pour cut-out: 1005,655 1010,660 1010,745 1005,750 745,750 740,745 740,660 745,655
  pour cut-out: 1050,925 1045,920 1045,835 1050,830 1205,830 1210,835 1210,920 1205,925
  pour cut-out: 615,105 620,100 880,100 885,105 885,365 880,370 535,370 530,365 530,295 535,290 610,290 615,285
  pour cut-out: 175,315 180,310 250,310 255,315 255,485 250,490 180,490 175,485
  pour cut-out: 430,130 435,135 435,215 430,220 340,220 335,215 335,135 340,130
Bottom Layer:
  pour cut-out: 1045,370 1050,365 1210,365 1215,370 1215,775 1210,780 1050,780 1045,775 1045,690 1050,685 1115,685 1120,680 1120,620 1115,615 1050,615 1045,610
  pour cut-out: 1055,930 1050,925 1050,840 1055,835 1210,835 1215,840 1215,925 1210,930
  pour cut-out: 357.07,795 353.54,793.54 336.47,776.46 335,772.93 335,392.07 336.47,388.54 388.54,336.46 392.07,335 475,335 480,340 480,790 475,795

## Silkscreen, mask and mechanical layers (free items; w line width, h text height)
Top Overlay, Top Silk:
  region: 997.5,420 1022.5,420 1022.5,395 997.5,395
  lines w5: 120,755 160,755 167.5,747.5 ; 390,370 390,395 ; 495,820 510,835 510,845 ; 600,187.5 610,200 ; 765,370 765,415
  text "HPA471B" at 875,25 h37.5
Bottom Overlay, Bot Silk:
  text ".PCB_Rev" at 330,275 h37.5
  text "REV" at 460,275 h37.5
  text ".PRJ_Number" at 1095,270 h37.5
M1 Board Outline:
  lines w5: 0,0 0,1100 1300,1100 1300,0 0,0
M5 Assembly Top:
  lines w10: -935,-1501.67 5665,-1501.67 ; -935,-1298.33 5667,-1298.33 ; -935,-1095 -935,-1705 3070,-1705 5667,-1705 5667,-1095 -934.5,-1095 -934.5,-1705 641,-1705 ; 1530,-1705 1530,-1095 ; 2797,-1298.33 2797,-1095 ; 3637,-1298.33 3637,-1095 ; 4259,-1711.5 4259,-1508.67
  text "COMPONENTS MARKED 'DNP' SHOULD NOT BE POPULATED." at 3725.5,2730 h60
  text "ASSEMBLY VARIANT:" at 3725,2614.5 h60
  text ".VariantName" at 4761,2614.5 h60
  text "PCB VIEWED FROM TOP SIDE" at -871.5,-1227.17 h60
  text "BOARD #:" at 1605,-1227.17 h60
  text ".PRJ_Number" at 2150.5,-1227.17 h60
  text "REV:" at 2995,-1227.17 h60
  text ".PCB_Rev" at 3286.5,-1227.17 h60
  text "SVN REV:" at 3833,-1227.17 h60
  text ".VersionControl_RevNumber" at 4339,-1227.17 h60
  text "IGNORE ->" at -871.5,-1429.99 h60
  text "PLOT NAME =" at -871.5,-1635.84 h60
  text ".plot_File_Name" at -66,-1635.84 h60
  text "GENERATED    :" at 1607,-1635.84 h60
  text ".Print_Date" at 2476.5,-1635.84 h60
  text ".Print_Time" at 3205.5,-1635.84 h60
  text "TEXAS INSTRUMENTS" at 4470,-1635.84 h60
M6 Assembly Bottom:
  lines w5: 20,95 20,20 95,20
M7 LPKF Text Top:
  lines w5: -100,0 25,0 ; 0,-100 0,25
M9 Title Sheet:
  drawing of 57 lines, arcs and shapes, not listed
  text "1" at 94.84,7461.5 h70
  text "2" at 2590.5,7461.5 h70
  text "3" at 5079.84,7461.5 h70
  text "4" at 7586.51,7461.5 h70
  text "5" at 10085.5,7461.5 h70
  text "6" at 12590.5,7461.5 h70
  text "A" at -1061.5,6318.5 h70
  text "A" at 13738.5,6318.5 h70
  text "B" at -1061.5,3938.5 h70
  text "B" at 13738.5,3938.5 h70
  text "C" at -1061.5,1563.5 h70
  text "C" at 13738.5,1563.5 h70
  text "PROJECT TITLE:" at 10698.5,-297.5 h45
  text ".PRJ_Title" at 10748.5,-430.83 h70
  text "DESIGNED FOR:" at 10698.5,-598.5 h45
  text ".PRJ_Customer" at 10748.5,-738.5 h70
  text "D" at -1061.5,-806.5 h70
  text "D" at 13738.5,-806.5 h70
  text "FILE NAME:" at 10698.5,-898.5 h45
  text ".PCB_File_Name_No_Path" at 10748.5,-1018.5 h70
  text "Texas Instruments (TI) and/or its licensors do not warrant the accuracy or completeness of this specification" at 5729,-1180.34 h45
  text "ENGINEER:" at 10698.5,-1188.5 h45
  text "LAYOUT BY:" at 12203.5,-1188.5 h45
  text "or any information contained therein. TI and/or its licensors do not warrant that this design will meet" at 5684.01,-1293 h45
  text ".PRJ_Engineer" at 10748.5,-1343.49 h70
  text ".PCB_Layout" at 12254,-1343.49 h70
  text "the specifications, will be suitable for your application or fit for any particular purpose, or will operate in" at 5684.01,-1405.67 h45
  text ".Layer_Name" at -68,-1433.49 h60
  text "ALTIUM DESIGNER VERSION:" at 12203.5,-1498.5 h45
  text "an implementation. TI and/or its licensors do not warrant that the design is production worthy. You should" at 5684.01,-1518.33 h45
  text "completely validate and test your design implementation to confirm the system functionality for your application." at 5729,-1631 h45
  text ".print_Scale" at 10748.5,-1631.83 h70
  text ".Application_BuildNumber" at 12254,-1631.83 h70
  text "1" at 94.84,-1838.5 h70
  text "2" at 2590.5,-1838.5 h70
  text "3" at 5079.84,-1838.5 h70
  text "4" at 7586.51,-1838.5 h70
  text "5" at 10085.5,-1838.5 h70
  text "6" at 12590.5,-1838.5 h70
M10 Fab Notes:
  drawing of 207 lines, arcs and shapes, not listed
  text "DESIGN INFORMATION" at 11738.52,6238.15 h60
  text "(REFER ALSO ARRAY/PANEL PROFILING INFORMATION)" at 11376.96,6076.43 h60
  text "BOARD SIZE" at 10690.96,6072.15 h60
  text "33.02mm" at 11153.28,5944.33 h60
  text "X" at 11658.96,5944.33 h60
  text "27.94mm" at 11890.28,5944.33 h60
  text "Number of Layers :" at 11093.96,5747.15 h60
  text "2" at 12188.77,5737.15 h60
  text "MIN. TRACK WIDTH:" at 11093.96,5608.15 h60
  text "10" at 12190.2,5608.15 h60
  text "MIL" at 12344.96,5608.15 h60
  text "MIN. CLEARANCE:" at 11093.96,5476.15 h60
  text "8" at 12190.2,5476.15 h60
  text "MIL" at 12344.96,5476.15 h60
  text "MIN. VIA PAD SIZE:" at 11093.96,5344.15 h60
  text "24" at 12160.21,5344.15 h60
  text "MIL" at 12344.96,5344.15 h60
  text "0.05mm (2MIL)" at 11788.96,5202.44 h60
  text "MINIMUM ANNULAR RING" at 10764.73,5198.15 h60
  text "EXTERNAL" at 12496.96,5198.15 h60
  text "PER" at 10964.73,5080.15 h60
  text "IPC-D-275 CLASS 2 LEVEL C" at 11184.73,5080.15 h60
  text "MIL, HOLES" at 12672.96,4967.86 h60
  text "+/-" at 12280.5,4967.15 h60
  text "+/-" at 13134.5,4967.15 h60
  text "REGISTRATION TOLERANCES:" at 10764.73,4962.15 h60
  text "METAL" at 11964.5,4962.15 h60
  text "5" at 12540.7,4962.15 h60
  text "5" at 13373.7,4962.15 h60
  text "MIL" at 13489.96,4962.15 h60
  text "MATERIAL:" at 10689.96,4752.69 h60
  text "FR-4 High Tg" at 11676.4,4612.36 h60
  text "X" at 11520.1,4606.02 h60
  text "FR-4" at 11150.96,4603.79 h60
  text "OTHER" at 12598.96,4603.79 h60
  text "62 MIL (1.6mm) +/-10%" at 11431.06,4441.07 h60
  text "THICKNESS:" at 10764.73,4436.79 h60
  text "X" at 11302.9,4436.79 h60
  text "OTHER" at 12715.96,4436.79 h60
  text "TOLERANCE:" at 10764.73,4278.79 h60
  text "X" at 11604.03,4278.79 h60
  text "ANSI IPC-6012 TYPE 3 CLASS 2" at 11790.98,4278.79 h60
  text "OTHER +/-" at 11790.96,4122.79 h60
  text "BOW & TWIST:" at 10764.73,3965.79 h60
  text "X" at 11604.03,3965.79 h60
  text "ANSI IPC-6012 TYPE 3 CLASS 2" at 11790.98,3965.79 h60
  text "OTHER +/-" at 11790.96,3807.28 h60
  text "COPPER THICKNESS (FINISHED):" at 10689.96,3671.79 h60
  text "X" at 12215,3525 h60
  text "2.8MIL (2oz)" at 12336.96,3524.29 h60
  text "1.4MIL (1oz)" at 11569.96,3519.07 h60
  text "4oz" at 13063.96,3519.07 h60
  text "OUTER:" at 11046.96,3514.79 h60
  text "1.4MIL (1oz)" at 11569.96,3362.07 h60
  text "2.8MIL (2oz)" at 12336.96,3362.07 h60
  text "N/A" at 13063.5,3362.43 h60
  text "X" at 12930,3360 h60
  text "INNER SIGNAL:" at 10757.88,3357.79 h60
  text "DRILLING:" at 10689.96,3218.79 h60
  text "REFERENCE:" at 10764.73,3101.79 h60
  text "X" at 11412.96,3101.79 h60
  text "AS SHOWN" at 11599.96,3101.79 h60
  text "X" at 12313.96,3101.79 h60
  text "NC_DRILL FILES" at 12450.96,3101.79 h60
  text "X" at 12642.22,2955.47 h60
  text "PTH MIN COPPER THICKNESS:" at 10764.73,2943.79 h60
  text "1MIL" at 12251.96,2943.79 h60
  text "1oz" at 12748.96,2943.79 h60
  text "BOARD FINISH:" at 10689.96,2784.79 h60
  text "SILKSCREEN:" at 10845.18,2666.79 h60
  text "X" at 11793.96,2666.79 h60
  text "TOP" at 11919.96,2666.79 h60
  text "X" at 12303.96,2666.79 h60
  text "BOTTOM" at 12430.96,2666.79 h60
  text "SILKSCREEN COLOR:" at 10845.18,2499.79 h60
  text "X" at 11792.92,2499.79 h60
  text "WHITE" at 11919.96,2499.79 h60
  text "OTHER" at 12430.96,2499.79 h60
  text "SOLDER RESIST COLOR:" at 10845.18,2329.79 h60
  text "X" at 11412.92,2170.59 h60
  text "GREEN" at 11539.96,2170.59 h60
  text "BLUE" at 12130.96,2170.59 h60
  text "OTHER" at 12668.96,2170.59 h60
  text "IMMERSION GOLD (ENIG)" at 11750.96,1982.07 h60
  text "X" at 11570,1980 h60
  text "SURFACE FINISH:" at 10689.96,1977.79 h60
  text "IMM. TIN/SILVER OR EQUIV" at 11019.5,1820.79 h60
  text "OTHER" at 12450.96,1820.79 h60
  text "ARRAY/PANEL:" at 10689.96,1641.79 h60
  text "CUT AND TRIM PER MECH LAYER 1" at 11750.96,1637.5 h60
  text "N.C. ROUTE" at 11750.96,1485.79 h60
  text "V. SCORE" at 12616.96,1485.79 h60
  text "X" at 12420.52,1474.79 h60
  text "CERTIFICATION:" at 10689.96,1348.79 h60
  text "MATERIALS AND WORKMANSHIP FOR ALL PCBS" at 11414.96,1348.79 h60
  text "TO MEET OR EXCEED THE REQUIREMENTS OF:" at 11414.96,1250.79 h60
  text "X" at 11041.46,1114.28 h60
  text "ANSI IPC-A-600F CLASS ->" at 11180.46,1114.28 h60
  text "X" at 12819.52,1114.28 h60
  text "2" at 12938.46,1114.28 h60
  text "1" at 12623.46,1112.79 h60
  text "3" at 13292.46,1112.79 h60
  text "X" at 11043.52,954.79 h60
  text "UL 94V-0" at 11180.46,954.79 h60
  text "X" at 11855.52,954.79 h60
  text "RoHS" at 11992.46,954.79 h60
  text "OTHER" at 12636.86,954.79 h60
  text "PER ORDER" at 13033.92,954.79 h60
  text "ADDITIONAL REQUIREMENTS:" at 10689.96,813.79 h60
  text "MICROSECTION:" at 10764.73,698.79 h60
  text "YES" at 11670.46,698.79 h60
  text "REQUIRED" at 12531.96,542.64 h60
  text "BARE BOARD ELEC. TEST:" at 10764.73,539.79 h60
  text "NONE" at 12070.46,539.79 h60
  text "PER ORDER" at 13123.96,539.79 h60
  text "X" at 12395,535 h60
  text "X" at 13092.22,385.47 h60
  text "MANUFACTURER'S ID/LOGO:" at 10764.73,382.79 h60
  text "RAIL" at 12230.46,378.5 h60
  text "METAL" at 12722.27,378.5 h60
  text "SILK" at 13233.96,378.5 h60
  text ".Layer_Name" at -65.5,-1430.34 h60
M11 Gerber Information:
  lines w10: -937,-1500.17 5663,-1500.17 ; -937,-1296.83 5665,-1296.83 ; -937,-1093.5 -937,-1703.5 3068,-1703.5 5665,-1703.5 5665,-1093.5 -936.5,-1093.5 -936.5,-1703.5 639,-1703.5 ; 1528,-1703.5 1528,-1093.5 ; 2795,-1296.83 2795,-1093.5 ; 3635,-1296.83 3635,-1093.5 ; 4257,-1710 4257,-1507.17
  text "ALL ARTWORK VIEWED FROM TOP SIDE" at -873.5,-1225.67 h60
  text "BOARD #:" at 1603,-1225.67 h60
  text ".PRJ_Number" at 2148.5,-1225.67 h60
  text "REV:" at 2993,-1225.67 h60
  text ".PCB_Rev" at 3284.5,-1225.67 h60
  text "SVN REV:" at 3831,-1225.67 h60
  text ".VersionControl_RevNumber" at 4337,-1225.67 h60
  text "LAYER NAME =" at -873.5,-1428.49 h60
  text "PLOT NAME =" at -873.5,-1634.34 h60
  text ".plot_File_Name" at -68,-1634.34 h60
  text "GENERATED    :" at 1605,-1634.34 h60
  text ".Print_Date" at 2474.5,-1634.34 h60
  text ".Print_Time" at 3203.5,-1634.34 h60
  text "TEXAS INSTRUMENTS" at 4468,-1634.34 h60
M12 Stackup:
  lines w8: 10770,6972.33 13505,6972.33 ; 10770,7127.93 13505,7127.93 ; 10710,6415 ccw(c10760,6415) 10760,6365 13515,6365 ccw(c13515,6415) 13565,6415 13565,7315 ccw(c13515,7315) 13515,7365 10760,7365 ccw(c10760,7315) 10710,7315 10710,6415
  text "Layer Stack Up Detail for: HPA471B.PcbDoc" at 10770,7198.47 h65
  text "Layer" at 10770,7069.93 h36
  text "Gerber" at 11814.03,7069.93 h36
  text "Copper" at 12278.64,7069.93 h36
  text "Dielectric" at 12802.03,7069.93 h36
  text "Name" at 10770,6997.93 h36
  text "Document" at 11814.03,6997.93 h36
  text "Thickness" at 12278.64,6997.93 h36
  text "Material" at 12802.03,6997.93 h36
  text "Top Solder Mask" at 10770,6856.77 h50
  text "(.GTS)" at 11814.03,6856.77 h50
  text "Solder Resist" at 12802.03,6856.77 h50
  text "Top Layer, Top" at 10770,6708.02 h50
  text "(.GTL)" at 11814.03,6708.02 h50
  text "2.8mil" at 12278.64,6708.02 h50
  text "FR-4" at 12802.03,6633.65 h50
  text "Bottom Layer, Bottom" at 10770,6559.27 h50
  text "(.GBL)" at 11814.03,6559.27 h50
  text "2.8mil" at 12278.64,6559.27 h50
  text "Bottom Solder Mask" at 10770,6410.52 h50
  text "(.GBS)" at 11814.03,6410.52 h50
  text "Solder Resist" at 12802.03,6410.52 h50
  text ".Layer_Name" at -68,-1428.49 h60
Drill Drawing:
  text ".legend" at 3564.55,1200.62 h60
  text "Drill Table" at 3589.55,1015.62 h60

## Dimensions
0,0 to 1300,0 on M2 Board Dimensions
0,1100 to 0,0 on M2 Board Dimensions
